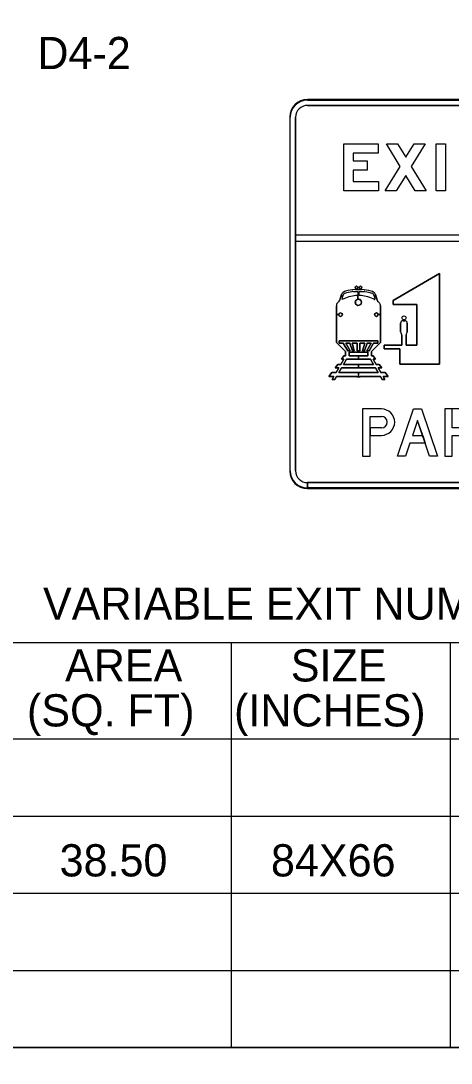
# Model space of a CAD drawing. Extents: x 0 to 2011, y -71 to 1183.
# Drawn here: x 320.2 to 362.9, y 598.9 to 702.5 of the extents above; entities that cross this region are included whole.
import ezdxf

# ---------------------------------------------------------------- set-up
doc = ezdxf.new("R2010")
doc.units = 0
for name, color, linetype in [('GSBWFILL', 7, 'Continuous'), ('Level 2', 7, 'Continuous'), ('Level 5', 7, 'Continuous')]:
    doc.layers.add(name, color=color, linetype=linetype)

msp = doc.modelspace()

# ---------------------------------------------------------------- linework, layer by layer
at = {"layer": 'GSBWFILL'}
for p, q in [((394.33, 694.68), (348.63, 694.68)), ((394.33, 694.68), (348.63, 694.68)), ((394.33, 694.68), (348.63, 694.68)), ((394.33, 694.68), (348.63, 694.68)), ((348.63, 694.62), (394.33, 694.62)), ((394.33, 694.1), (348.63, 694.1)), ((348.63, 694.1), (394.33, 694.1)), ((348.63, 694.1), (394.33, 694.1)), ((346.87, 692.93), (346.87, 657.77)), ((346.87, 692.93), (346.87, 657.77)), ((346.87, 692.93), (346.87, 657.77)), ((346.87, 692.93), (346.87, 657.77)), ((346.93, 657.77), (346.93, 692.93)), ((347.45, 692.93), (347.45, 657.77)), ((347.45, 657.77), (347.45, 692.93)), ((347.45, 657.77), (347.45, 692.93)), ((395.5, 681.21), (347.45, 681.21)), ((347.45, 681.21), (347.45, 680.62)), ((395.5, 681.21), (347.45, 681.21)), ((347.45, 681.21), (347.45, 680.62)), ((395.5, 681.21), (347.45, 681.21)), ((347.45, 681.21), (347.45, 680.62)), ((347.45, 680.62), (395.5, 680.62)), ((347.45, 680.62), (395.5, 680.62)), ((347.45, 680.62), (395.5, 680.62)), ((354.86, 663.17), (355.99, 663.17)), ((354.86, 663.17), (355.99, 663.17)), ((354.86, 661.3), (355.99, 661.3)), ((348.63, 656.6), (394.33, 656.6)), ((348.63, 656.01), (348.63, 656.6)), ((394.33, 656.6), (348.63, 656.6)), ((348.63, 656.6), (348.63, 656.01)), ((348.63, 656.01), (348.63, 656.6)), ((394.33, 656.6), (348.63, 656.6)), ((348.63, 656.6), (348.63, 656.01)), ((348.63, 656.01), (348.63, 656.07)), ((394.33, 656.07), (348.63, 656.07)), ((348.63, 656.07), (348.63, 656.01)), ((348.63, 656.01), (394.33, 656.01)), ((348.63, 656.01), (394.33, 656.01)), ((348.63, 656.01), (394.33, 656.01)), ((348.63, 656.01), (394.33, 656.01))]:
    msp.add_line(p, q, dxfattribs=at)
for points in [[(355.66, 690.29), (355.66, 689.35), (353.17, 689.35), (353.17, 688.6), (354.58, 688.6), (354.58, 687.66), (353.17, 687.66), (353.17, 686.54), (355.7, 686.54), (355.7, 685.6), (352.24, 685.6), (352.24, 690.29)], [(355.66, 690.29), (355.66, 689.35), (353.17, 689.35), (353.17, 688.6), (354.58, 688.6), (354.58, 687.66), (353.17, 687.66), (353.17, 686.54), (355.7, 686.54), (355.7, 685.6), (352.24, 685.6), (352.24, 690.29)], [(355.66, 690.29), (355.66, 689.35), (353.17, 689.35), (353.17, 688.6), (354.58, 688.6), (354.58, 687.66), (353.17, 687.66), (353.17, 686.54), (355.7, 686.54), (355.7, 685.6), (352.24, 685.6), (352.24, 690.29)], [(359.34, 685.6), (358.4, 687.14), (357.46, 685.6), (356.36, 685.6), (357.85, 688.04), (356.48, 690.29), (357.58, 690.29), (358.4, 688.94), (359.22, 690.29), (360.32, 690.29), (358.95, 688.04), (360.44, 685.6)], [(359.34, 685.6), (358.4, 687.14), (357.46, 685.6), (356.36, 685.6), (357.85, 688.04), (356.48, 690.29), (357.58, 690.29), (358.4, 688.94), (359.22, 690.29), (360.32, 690.29), (358.95, 688.04), (360.44, 685.6)], [(359.34, 685.6), (358.4, 687.14), (357.46, 685.6), (356.36, 685.6), (357.85, 688.04), (356.48, 690.29), (357.58, 690.29), (358.4, 688.94), (359.22, 690.29), (360.32, 690.29), (358.95, 688.04), (360.44, 685.6)], [(361.42, 690.29), (362.36, 690.29), (362.36, 685.6), (361.42, 685.6)], [(361.42, 690.29), (362.36, 690.29), (362.36, 685.6), (361.42, 685.6)], [(361.42, 690.29), (362.36, 690.29), (362.36, 685.6), (361.42, 685.6)], [(353.7, 670.69), (351.78, 670.69), (351.78, 670.48), (352.19, 670.48), (352.65, 669.7), (352.87, 669.7), (352.46, 670.48), (352.85, 670.48), (353.11, 669.7), (353.29, 669.7), (353.08, 670.48), (353.58, 670.48), (353.58, 669.7), (353.7, 669.7), (353.83, 669.7), (353.83, 670.48), (354.32, 670.48), (354.12, 669.7), (354.3, 669.7), (354.56, 670.48), (354.95, 670.48), (354.54, 669.7), (354.75, 669.7), (355.21, 670.48), (355.62, 670.48), (355.62, 670.69)], [(352.77, 669.2), (354.63, 669.2), (354.63, 669.57), (352.77, 669.57)], [(352.51, 668.89), (352.21, 668.35), (355.2, 668.35), (354.9, 668.89)], [(352.02, 668.02), (351.74, 667.54), (355.67, 667.54), (355.4, 668.02)], [(358.81, 660.52), (358.37, 659.23), (357.58, 659.23), (359.17, 663.92), (359.97, 663.92), (361.56, 659.23), (360.77, 659.23), (360.33, 660.52)], [(357.58, 659.23), (359.17, 663.92), (359.97, 663.92), (361.56, 659.23), (360.77, 659.23), (359.57, 662.76), (359.06, 661.27), (360.08, 661.27), (360.33, 660.52), (358.81, 660.52), (358.37, 659.23)], [(357.58, 659.23), (359.17, 663.92), (359.97, 663.92), (361.56, 659.23), (360.77, 659.23), (359.57, 662.76), (359.06, 661.27), (360.08, 661.27), (360.33, 660.52), (358.81, 660.52), (358.37, 659.23)], [(359.06, 661.27), (360.08, 661.27), (359.57, 662.76)]]:
    msp.add_lwpolyline(points, close=True, dxfattribs=at)
for points in [[(358, 671.29), (358, 670.27), (356.24, 670.27), (356.24, 670.12), (356.27, 670.1), (356.27, 669.91), (357.8, 669.91), (357.8, 668.38), (361.76, 668.38), (361.76, 677.4), (357.14, 674.7), (357.14, 674.31), (359.51, 674.31), (359.51, 670.27), (358.43, 670.27), (358.43, 671.29)], [(358.43, 671.29), (358.43, 670.27), (359.51, 670.27), (359.51, 674.31), (357.14, 674.31), (357.14, 674.7), (361.76, 677.4), (361.76, 668.38), (357.8, 668.38), (357.8, 669.91), (356.27, 669.91), (356.27, 670.1), (356.24, 670.12), (356.24, 670.27), (358, 670.27), (358, 671.29)], [(358.43, 671.29), (358.43, 670.27), (359.51, 670.27), (359.51, 674.31), (357.14, 674.31), (357.14, 674.7), (361.76, 677.4), (361.76, 668.38), (357.8, 668.38), (357.8, 669.91), (356.27, 669.91), (356.27, 670.1), (356.24, 670.12), (356.24, 670.27), (358, 670.27), (358, 671.29)], [(353.41, 675.81), (353.7, 675.81), (353.99, 675.81)], [(353.99, 675.81), (353.41, 675.81)], [(353.99, 675.81), (353.41, 675.81)], [(351.85, 674.75), (352.01, 675.29)], [(352.07, 674.84), (352.15, 675.13), (351.96, 675.13), (351.85, 674.75)], [(352.07, 674.84), (352.15, 675.13), (351.96, 675.13), (351.85, 674.75)], [(352.01, 675.29), (351.96, 675.13), (352.15, 675.13), (352.18, 675.24)], [(352.01, 675.29), (351.96, 675.13), (352.15, 675.13), (352.18, 675.24)], [(352.07, 674.84), (352.18, 675.24)], [(353.13, 675.6), (353.63, 675.6), (353.63, 675.21), (353.47, 675.21)], [(353.13, 675.6), (353.63, 675.6), (353.63, 674.83)], [(353.13, 675.6), (353.63, 675.6), (353.63, 674.83)], [(353.63, 674.83), (353.63, 675.21), (353.47, 675.21)], [(353.63, 674.83), (353.63, 675.21), (353.47, 675.21)], [(353.93, 675.21), (353.77, 675.21), (353.77, 675.6), (354.28, 675.6)], [(353.93, 675.21), (353.77, 675.21), (353.77, 675.6), (354.28, 675.6)], [(353.93, 675.21), (353.77, 675.21), (353.77, 675.6), (354.28, 675.6)], [(355.22, 675.24), (355.25, 675.13), (355.44, 675.13), (355.4, 675.29)], [(355.22, 675.24), (355.25, 675.13), (355.44, 675.13), (355.4, 675.29)], [(355.22, 675.24), (355.34, 674.84)], [(355.55, 674.75), (355.44, 675.13), (355.25, 675.13), (355.34, 674.84)], [(355.55, 674.75), (355.44, 675.13), (355.25, 675.13), (355.34, 674.84)], [(355.4, 675.29), (355.55, 674.75)], [(355.9, 674.18), (355.9, 670.54), (355, 669.65), (355, 669.2), (355.15, 669.2), (355.38, 668.89), (355.16, 668.89), (355.46, 668.35), (355.77, 668.35), (356.01, 668.02), (355.65, 668.02), (355.93, 667.54), (356.36, 667.54), (356.64, 667.15), (356.15, 667.15), (356.32, 666.85), (356.06, 666.85), (355.89, 667.15), (353.86, 667.15), (353.86, 667.12), (353.7, 667.12), (353.55, 667.12), (353.55, 667.15), (351.52, 667.15), (351.35, 666.85), (351.09, 666.85), (351.26, 667.15), (350.76, 667.15), (351.05, 667.54), (351.49, 667.54), (351.76, 668.02), (351.39, 668.02), (351.64, 668.35), (351.95, 668.35), (352.26, 668.89), (352.03, 668.89), (352.25, 669.2), (352.4, 669.2), (352.4, 669.65), (351.51, 670.54), (351.51, 674.18)], [(351.51, 674.18), (351.51, 673.3), (351.74, 673.3)], [(351.51, 674.18), (351.51, 673.3), (351.74, 673.3)], [(355.66, 673.3), (355.9, 673.3), (355.9, 674.18)], [(355.66, 673.3), (355.9, 673.3), (355.9, 674.18)], [(352.4, 669.2), (352.25, 669.2), (352.03, 668.89), (352.26, 668.89), (351.95, 668.35), (351.64, 668.35), (351.39, 668.02), (351.76, 668.02), (351.49, 667.54), (351.05, 667.54), (350.76, 667.15), (351.26, 667.15), (351.09, 666.85), (351.35, 666.85), (351.52, 667.15), (353.55, 667.15), (353.55, 667.12), (353.7, 667.12), (353.7, 667.54), (351.74, 667.54), (352.02, 668.02), (353.7, 668.02), (353.7, 668.35), (352.21, 668.35), (352.51, 668.89), (353.7, 668.89), (353.7, 669.2), (352.77, 669.2), (352.77, 669.57), (353.7, 669.57), (353.7, 669.7), (353.58, 669.7), (353.58, 670.48), (353.08, 670.48), (353.29, 669.7), (353.11, 669.7), (352.85, 670.48), (352.46, 670.48), (352.87, 669.7), (352.65, 669.7), (352.19, 670.48), (351.78, 670.48), (351.78, 670.69), (353.7, 670.69), (355.62, 670.69), (355.62, 670.48), (355.21, 670.48), (354.75, 669.7), (354.54, 669.7), (354.95, 670.48), (354.56, 670.48), (354.3, 669.7), (354.12, 669.7), (354.32, 670.48), (353.83, 670.48), (353.83, 669.7), (353.7, 669.7), (353.7, 669.57), (354.63, 669.57), (354.63, 669.2), (353.7, 669.2), (353.7, 668.89), (354.9, 668.89), (355.2, 668.35), (353.7, 668.35), (353.7, 668.02), (355.4, 668.02), (355.67, 667.54), (353.7, 667.54), (353.7, 667.12), (353.86, 667.12), (353.86, 667.15), (355.89, 667.15), (356.06, 666.85), (356.32, 666.85), (356.15, 667.15), (356.64, 667.15), (356.36, 667.54), (355.93, 667.54), (355.65, 668.02), (356.01, 668.02), (355.77, 668.35), (355.46, 668.35), (355.16, 668.89), (355.38, 668.89), (355.15, 669.2), (355, 669.2), (355, 669.65), (355.9, 670.54), (355.9, 673.3), (355.66, 673.3)], [(352.4, 669.2), (352.25, 669.2), (352.03, 668.89), (352.26, 668.89), (351.95, 668.35), (351.64, 668.35), (351.39, 668.02), (351.76, 668.02), (351.49, 667.54), (351.05, 667.54), (350.76, 667.15), (351.26, 667.15), (351.09, 666.85), (351.35, 666.85), (351.52, 667.15), (353.55, 667.15), (353.55, 667.12), (353.7, 667.12), (353.7, 667.54), (351.74, 667.54), (352.02, 668.02), (353.7, 668.02), (353.7, 668.35), (352.21, 668.35), (352.51, 668.89), (353.7, 668.89), (353.7, 669.2), (352.77, 669.2), (352.77, 669.57), (353.7, 669.57), (353.7, 669.7), (353.58, 669.7), (353.58, 670.48), (353.08, 670.48), (353.29, 669.7), (353.11, 669.7), (352.85, 670.48), (352.46, 670.48), (352.87, 669.7), (352.65, 669.7), (352.19, 670.48), (351.78, 670.48), (351.78, 670.69), (353.7, 670.69), (355.62, 670.69), (355.62, 670.48), (355.21, 670.48), (354.75, 669.7), (354.54, 669.7), (354.95, 670.48), (354.56, 670.48), (354.3, 669.7), (354.12, 669.7), (354.32, 670.48), (353.83, 670.48), (353.83, 669.7), (353.7, 669.7), (353.7, 669.57), (354.63, 669.57), (354.63, 669.2), (353.7, 669.2), (353.7, 668.89), (354.9, 668.89), (355.2, 668.35), (353.7, 668.35), (353.7, 668.02), (355.4, 668.02), (355.67, 667.54), (353.7, 667.54), (353.7, 667.12), (353.86, 667.12), (353.86, 667.15), (355.89, 667.15), (356.06, 666.85), (356.32, 666.85), (356.15, 667.15), (356.64, 667.15), (356.36, 667.54), (355.93, 667.54), (355.65, 668.02), (356.01, 668.02), (355.77, 668.35), (355.46, 668.35), (355.16, 668.89), (355.38, 668.89), (355.15, 669.2), (355, 669.2), (355, 669.65), (355.9, 670.54), (355.9, 673.3), (355.66, 673.3)], [(351.74, 673.3), (351.51, 673.3), (351.51, 670.54), (352.4, 669.65), (352.4, 669.2)], [(351.74, 673.3), (351.51, 673.3), (351.51, 670.54), (352.4, 669.65), (352.4, 669.2)], [(358.3, 672.69), (358.13, 672.69)], [(358.13, 672.69), (358.3, 672.69)], [(358.13, 672.69), (358.3, 672.69)], [(357.89, 672.45), (357.89, 671.59)], [(357.89, 671.59), (357.89, 672.45)], [(357.89, 671.59), (357.89, 672.45)], [(358.54, 671.59), (358.54, 672.45)], [(358.54, 672.45), (358.54, 671.59)], [(358.54, 672.45), (358.54, 671.59)], [(357.94, 671.45), (357.95, 671.43)], [(357.95, 671.43), (357.94, 671.45)], [(357.95, 671.43), (357.94, 671.45)], [(358.48, 671.43), (358.49, 671.44)], [(358.49, 671.44), (358.48, 671.43)], [(358.49, 671.44), (358.48, 671.43)], [(355.99, 663.92), (354.11, 663.92), (354.11, 659.23), (354.86, 659.23), (354.86, 661.3)], [(355.99, 663.92), (354.11, 663.92), (354.11, 659.23), (354.86, 659.23), (354.86, 663.17)], [(355.99, 663.92), (354.11, 663.92), (354.11, 659.23), (354.86, 659.23), (354.86, 663.17)], [(364.05, 662.05), (363.02, 662.05), (363.02, 663.92), (362.27, 663.92), (362.27, 659.23), (363.02, 659.23), (363.02, 661.3), (363.9, 661.3), (364.65, 659.23), (365.45, 659.23), (364.64, 661.44)], [(364.05, 662.05), (363.02, 662.05), (363.02, 663.92), (362.27, 663.92), (362.27, 659.23), (363.02, 659.23), (363.02, 661.3), (363.9, 661.3), (364.65, 659.23), (365.45, 659.23), (364.64, 661.44)], [(364.05, 663.92), (362.27, 663.92), (362.27, 659.23), (363.02, 659.23), (363.02, 661.3), (363.9, 661.3), (364.65, 659.23), (365.45, 659.23), (364.64, 661.44)], [(355.99, 662.05), (354.86, 662.05), (354.86, 663.17), (355.99, 663.17)], [(355.99, 662.05), (354.86, 662.05), (354.86, 661.3), (355.99, 661.3)], [(355.99, 662.05), (354.86, 662.05), (354.86, 661.3), (355.99, 661.3)]]:
    msp.add_lwpolyline(points, dxfattribs=at)
for centre, radius in [((353.51, 676.02), 0.128), ((353.51, 676.02), 0.128), ((353.51, 676.02), 0.128), ((353.9, 676.02), 0.128), ((353.9, 676.02), 0.128), ((353.9, 676.02), 0.128), ((353.7, 674.53), 0.312), ((351.92, 673.3), 0.183), ((355.48, 673.3), 0.183), ((358.23, 672.98), 0.198), ((358.23, 672.98), 0.198), ((358.23, 672.98), 0.198)]:
    msp.add_circle(centre, radius, dxfattribs=at)
for centre, radius, start, end in [((348.63, 692.93), 1.76, 90, 180), ((348.63, 692.93), 1.76, 90, 180), ((348.63, 692.93), 1.76, 90, 180), ((348.63, 692.93), 1.76, 90, 180), ((348.63, 692.93), 1.7, 90, 180), ((348.63, 692.93), 1.17, 90, 180), ((348.63, 692.93), 1.17, 90, 180), ((348.63, 692.93), 1.17, 90, 180), ((352.64, 674.81), 0.854, 104.0733, 120.6228), ((352.64, 674.81), 0.854, 104.0733, 120.6228), ((352.64, 674.81), 0.854, 104.0733, 120.6228), ((353.7, 671.38), 4.44, 94.4231, 106.6457), ((353.7, 671.38), 4.44, 94.4231, 106.6457), ((353.7, 671.38), 4.44, 94.4231, 106.6457), ((353.41, 675.15), 0.664, 90, 94.4231), ((353.41, 675.15), 0.664, 90, 94.4231), ((353.41, 675.15), 0.664, 90, 94.4231), ((353.99, 675.15), 0.664, 85.5769, 90), ((353.99, 675.15), 0.664, 85.5769, 90), ((353.99, 675.15), 0.664, 85.5769, 90), ((353.7, 671.38), 4.44, 73.3543, 85.5769), ((353.7, 671.38), 4.44, 73.3543, 85.5769), ((353.7, 671.38), 4.44, 73.3543, 85.5769), ((354.76, 674.81), 0.854, 59.3772, 75.9267), ((354.76, 674.81), 0.854, 59.3772, 75.9267), ((354.76, 674.81), 0.854, 59.3772, 75.9267), ((351.51, 674.85), 0.354, 305.9613, 343.6111), ((351.51, 674.85), 0.354, 305.9613, 343.6111), ((351.51, 674.85), 0.354, 305.9613, 343.6111), ((352.43, 675.16), 0.442, 120.6228, 163.6111), ((352.43, 675.16), 0.442, 120.6228, 163.6111), ((352.43, 675.16), 0.442, 120.6228, 163.6111), ((352.09, 674.83), 0.0221, 163.6111, 294.5458), ((352.09, 674.83), 0.0221, 163.6111, 294.5458), ((352.09, 674.83), 0.0221, 163.6111, 294.5458), ((354.18, 670.23), 5.03, 98.3195, 114.4303), ((354.18, 670.23), 5.03, 98.3195, 114.4303), ((354.18, 670.23), 5.03, 98.3195, 114.4303), ((352.44, 675.17), 0.265, 108.4965, 163.6111), ((352.44, 675.17), 0.265, 108.4965, 163.6111), ((352.44, 675.17), 0.265, 108.4965, 163.6111), ((353.7, 671.38), 4.25, 98.7382, 108.4965), ((353.7, 671.38), 4.25, 98.7382, 108.4965), ((353.7, 671.38), 4.25, 98.7382, 108.4965), ((353.13, 675.15), 0.442, 90, 98.7382), ((353.13, 675.15), 0.442, 90, 98.7382), ((353.13, 675.15), 0.442, 90, 98.7382), ((353.7, 674.53), 0.312, 103.0053, 102.9221), ((353.7, 674.53), 0.312, 103.0053, 102.9221), ((353.47, 675.04), 0.177, 90, 98.3195), ((353.47, 675.04), 0.177, 90, 98.3195), ((353.47, 675.04), 0.177, 90, 98.3195), ((353.93, 675.04), 0.177, 81.6805, 90), ((353.93, 675.04), 0.177, 81.6805, 90), ((353.93, 675.04), 0.177, 81.6805, 90), ((353.23, 670.23), 5.03, 65.5697, 81.6805), ((353.23, 670.23), 5.03, 65.5697, 81.6805), ((353.23, 670.23), 5.03, 65.5697, 81.6805), ((354.28, 675.15), 0.442, 81.2618, 90), ((354.28, 675.15), 0.442, 81.2618, 90), ((354.28, 675.15), 0.442, 81.2618, 90), ((353.7, 671.38), 4.25, 71.5035, 81.2618), ((353.7, 671.38), 4.25, 71.5035, 81.2618), ((353.7, 671.38), 4.25, 71.5035, 81.2618), ((354.97, 675.17), 0.265, 16.3889, 71.5035), ((354.97, 675.17), 0.265, 16.3889, 71.5035), ((354.97, 675.17), 0.265, 16.3889, 71.5035), ((354.97, 675.16), 0.442, 16.3889, 59.3772), ((354.97, 675.16), 0.442, 16.3889, 59.3772), ((354.97, 675.16), 0.442, 16.3889, 59.3772), ((355.32, 674.83), 0.0221, 245.4542, 16.3889), ((355.32, 674.83), 0.0221, 245.4542, 16.3889), ((355.32, 674.83), 0.0221, 245.4542, 16.3889), ((355.89, 674.85), 0.354, 196.3889, 234.0387), ((355.89, 674.85), 0.354, 196.3889, 234.0387), ((355.89, 674.85), 0.354, 196.3889, 234.0387), ((351.95, 674.18), 0.442, 141.4354, 180), ((351.95, 674.18), 0.442, 141.4354, 180), ((351.95, 674.18), 0.442, 141.4354, 180), ((352.06, 674.09), 0.588, 125.9613, 141.4354), ((352.06, 674.09), 0.588, 125.9613, 141.4354), ((352.06, 674.09), 0.588, 125.9613, 141.4354), ((355.34, 674.09), 0.588, 38.5646, 54.0387), ((355.34, 674.09), 0.588, 38.5646, 54.0387), ((355.34, 674.09), 0.588, 38.5646, 54.0387), ((355.45, 674.18), 0.442, 0, 38.5646), ((355.45, 674.18), 0.442, 0, 38.5646), ((355.45, 674.18), 0.442, 0, 38.5646), ((351.92, 673.3), 0.183, 180.0691, 179.9309), ((351.92, 673.3), 0.183, 180.0691, 179.9309), ((355.48, 673.3), 0.183, 0.0691, 359.9309), ((355.48, 673.3), 0.183, 0.0691, 359.9309), ((358.13, 672.45), 0.243, 90, 180), ((358.13, 672.45), 0.243, 90, 180), ((358.13, 672.45), 0.243, 90, 180), ((358.3, 672.45), 0.243, 0, 90), ((358.3, 672.45), 0.243, 0, 90), ((358.3, 672.45), 0.243, 0, 90), ((358.11, 671.59), 0.221, 180, 220.0861), ((358.11, 671.59), 0.221, 180, 220.0861), ((358.11, 671.59), 0.221, 180, 220.0861), ((358.32, 671.59), 0.221, 319.9139, 0), ((358.32, 671.59), 0.221, 319.9139, 0), ((358.32, 671.59), 0.221, 319.9139, 360), ((357.78, 671.29), 0.221, 360, 40.0861), ((357.78, 671.29), 0.221, 0, 40.0861), ((357.78, 671.29), 0.221, 0, 40.0861), ((358.65, 671.29), 0.221, 139.9139, 180), ((358.65, 671.29), 0.221, 139.9139, 180), ((358.65, 671.29), 0.221, 139.9139, 180), ((355.99, 662.61), 1.31, 270, 90), ((355.99, 662.61), 1.31, 270, 90), ((355.99, 662.61), 1.31, 270, 90), ((355.99, 662.61), 0.562, 270, 90), ((355.99, 662.61), 0.562, 270, 90), ((355.99, 662.61), 0.562, 270, 90), ((348.63, 657.77), 1.76, 180, 270), ((348.63, 657.77), 1.76, 180, 270), ((348.63, 657.77), 1.76, 180, 270), ((348.63, 657.77), 1.76, 180, 270), ((348.63, 657.77), 1.7, 180, 270), ((348.63, 657.77), 1.17, 180, 270), ((348.63, 657.77), 1.17, 180, 270), ((348.63, 657.77), 1.17, 180, 270)]:
    msp.add_arc(centre, radius, start, end, dxfattribs=at)
at = {"layer": 'Level 2'}
for p, q in [((319.3, 640.71), (424.05, 640.71)), ((341.05, 640.71), (341.05, 600.44)), ((362.8, 640.71), (362.8, 600.44)), ((319.3, 631.12), (424.05, 631.12)), ((319.3, 623.45), (424.05, 623.45)), ((319.3, 615.78), (424.05, 615.78)), ((319.3, 608.11), (424.05, 608.11))]:
    msp.add_line(p, q, dxfattribs=at)
for points in [[(424.05, 704.06), (319.3, 704.06), (319.3, 600.44), (424.05, 600.44)], [(424.05, 600.44), (319.3, 600.44), (319.3, 496.81), (424.05, 496.81)]]:
    msp.add_lwpolyline(points, close=True, dxfattribs=at)

# ---------------------------------------------------------------- texts
for s, p in [('D4-2', (321.81, 697.71)), ('VARIABLE EXIT NUMBER', (322.37, 642.97)), ('AREA', (324.56, 636.83)), ('SIZE', (346.98, 636.83)), ('(SQ. FT)', (320.78, 632.36)), ('(INCHES)', (341.35, 632.36))]:
    msp.add_text(s, height=3.2, dxfattribs=at).set_placement(p)
at = {"layer": 'Level 5'}
for s, p in [('38.50', (324.02, 617.45)), ('84X66', (345.01, 617.45))]:
    msp.add_text(s, height=3.2, dxfattribs=at).set_placement(p)

doc.saveas('drawing.dxf')
